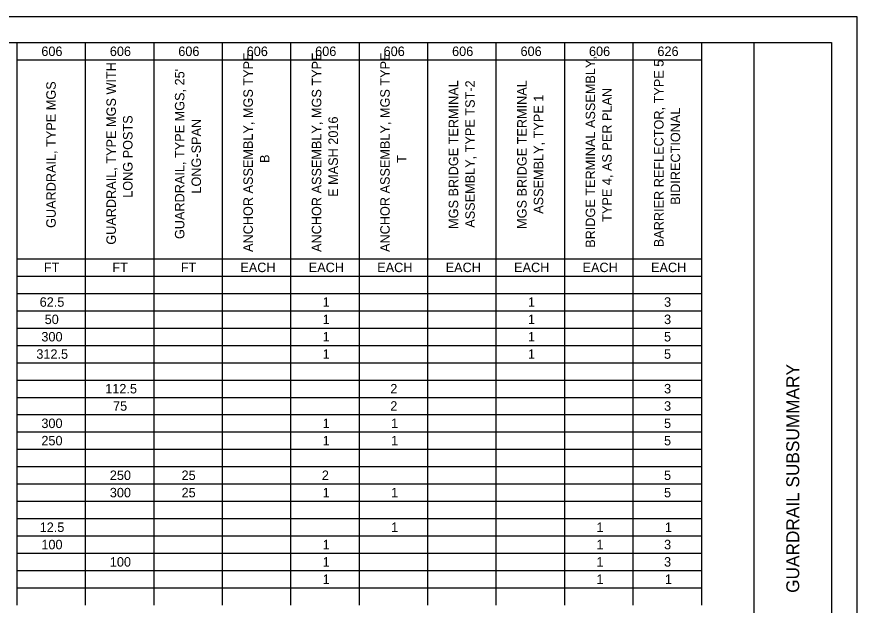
# Model space of a CAD drawing. Extents: x 0 to 34, y 0 to 22.
# Drawn here: x 17.69 to 34, y 10.59 to 22 of the extents above; entities that cross this region are included whole.
import ezdxf

# ---------------------------------------------------------------- set-up
doc = ezdxf.new("R2010")
doc.units = 0
for name, color, linetype in [('SH_Border', 7, 'Continuous'), ('SH_Cut_Line', 7, 'Continuous'), ('SH_Data', 7, 'Continuous'), ('SH_Text', 7, 'Continuous')]:
    doc.layers.add(name, color=color, linetype=linetype)

msp = doc.modelspace()

# ---------------------------------------------------------------- linework, layer by layer
at = {"layer": 'SH_Border'}
msp.add_line((32, 0.5), (32, 21.5), dxfattribs=at)
msp.add_lwpolyline([(1.5, 21.5), (33.5, 21.5), (33.5, 0.5), (1.5, 0.5)], close=True, dxfattribs=at)
at = {"layer": 'SH_Cut_Line'}
msp.add_lwpolyline([(0, 0), (34, 0), (34, 22), (0, 22)], close=True, dxfattribs=at)
at = {"layer": 'SH_Text'}
for p, q in [((17.694, 21.499), (19.022, 21.499)), ((17.694, 21.499), (17.694, 21.163)), ((19.022, 21.499), (28.32, 21.499)), ((19.022, 21.499), (19.022, 21.163)), ((20.35, 21.499), (20.35, 21.163)), ((21.679, 21.499), (21.679, 21.163)), ((23.007, 21.499), (23.007, 21.163)), ((24.335, 21.499), (24.335, 21.163)), ((25.663, 21.499), (25.663, 21.163)), ((26.991, 21.499), (26.991, 21.163)), ((28.32, 21.499), (29.648, 21.499)), ((28.32, 21.499), (28.32, 21.163)), ((29.648, 21.499), (30.976, 21.499)), ((29.648, 21.499), (29.648, 21.163)), ((30.976, 21.499), (30.976, 21.163)), ((17.694, 21.163), (19.022, 21.163)), ((17.694, 21.163), (17.694, 20.827)), ((19.022, 21.163), (28.32, 21.163)), ((19.022, 21.163), (19.022, 20.827)), ((20.35, 21.163), (20.35, 20.827)), ((21.679, 21.163), (21.679, 20.827)), ((23.007, 21.163), (23.007, 20.827)), ((24.335, 21.163), (24.335, 20.827)), ((25.663, 21.163), (25.663, 20.827)), ((26.991, 21.163), (26.991, 20.827)), ((28.32, 21.163), (29.648, 21.163)), ((28.32, 21.163), (28.32, 20.827)), ((29.648, 21.163), (30.976, 21.163)), ((29.648, 21.163), (29.648, 20.827)), ((30.976, 21.163), (30.976, 20.827)), ((17.694, 20.827), (17.694, 20.491)), ((19.022, 20.827), (19.022, 20.491)), ((20.35, 20.827), (20.35, 20.491)), ((21.679, 20.827), (21.679, 20.491)), ((23.007, 20.827), (23.007, 20.491)), ((24.335, 20.827), (24.335, 20.491)), ((25.663, 20.827), (25.663, 20.491)), ((26.991, 20.827), (26.991, 20.491)), ((28.32, 20.827), (28.32, 20.491)), ((29.648, 20.827), (29.648, 20.491)), ((30.976, 20.827), (30.976, 20.491)), ((17.694, 20.491), (17.694, 20.155)), ((19.022, 20.491), (19.022, 20.155)), ((20.35, 20.491), (20.35, 20.155)), ((21.679, 20.491), (21.679, 20.155)), ((23.007, 20.491), (23.007, 20.155)), ((24.335, 20.491), (24.335, 20.155)), ((25.663, 20.491), (25.663, 20.155)), ((26.991, 20.491), (26.991, 20.155)), ((28.32, 20.491), (28.32, 20.155)), ((29.648, 20.491), (29.648, 20.155)), ((30.976, 20.491), (30.976, 20.155)), ((17.694, 20.155), (17.694, 19.819)), ((19.022, 20.155), (19.022, 19.819)), ((20.35, 20.155), (20.35, 19.819)), ((21.679, 20.155), (21.679, 19.819)), ((23.007, 20.155), (23.007, 19.819)), ((24.335, 20.155), (24.335, 19.819)), ((25.663, 20.155), (25.663, 19.819)), ((26.991, 20.155), (26.991, 19.819)), ((28.32, 20.155), (28.32, 19.819)), ((29.648, 20.155), (29.648, 19.819)), ((30.976, 20.155), (30.976, 19.819)), ((17.694, 19.819), (17.694, 19.483)), ((19.022, 19.819), (19.022, 19.483)), ((20.35, 19.819), (20.35, 19.483)), ((21.679, 19.819), (21.679, 19.483)), ((23.007, 19.819), (23.007, 19.483)), ((24.335, 19.819), (24.335, 19.483)), ((25.663, 19.819), (25.663, 19.483)), ((26.991, 19.819), (26.991, 19.483)), ((28.32, 19.819), (28.32, 19.483)), ((29.648, 19.819), (29.648, 19.483)), ((30.976, 19.819), (30.976, 19.483)), ((17.694, 19.483), (17.694, 19.147)), ((19.022, 19.483), (19.022, 19.147)), ((20.35, 19.483), (20.35, 19.147)), ((21.679, 19.483), (21.679, 19.147)), ((23.007, 19.483), (23.007, 19.147)), ((24.335, 19.483), (24.335, 19.147)), ((25.663, 19.483), (25.663, 19.147)), ((26.991, 19.483), (26.991, 19.147)), ((28.32, 19.483), (28.32, 19.147)), ((29.648, 19.483), (29.648, 19.147)), ((30.976, 19.483), (30.976, 19.147)), ((17.694, 19.147), (17.694, 18.315)), ((19.022, 19.147), (19.022, 18.315)), ((20.35, 19.147), (20.35, 18.315)), ((21.679, 19.147), (21.679, 18.315)), ((23.007, 19.147), (23.007, 18.315)), ((24.335, 19.147), (24.335, 18.315)), ((25.663, 19.147), (25.663, 18.315)), ((26.991, 19.147), (26.991, 18.315)), ((28.32, 19.147), (28.32, 18.315)), ((29.648, 19.147), (29.648, 18.315)), ((30.976, 19.147), (30.976, 18.315)), ((17.694, 18.315), (17.694, 17.307)), ((19.022, 18.315), (19.022, 17.307)), ((20.35, 18.315), (20.35, 17.307)), ((21.679, 18.315), (21.679, 17.307)), ((23.007, 18.315), (23.007, 17.307)), ((24.335, 18.315), (24.335, 17.307)), ((25.663, 18.315), (25.663, 17.307)), ((26.991, 18.315), (26.991, 17.307)), ((28.32, 18.315), (28.32, 17.307)), ((29.648, 18.315), (29.648, 17.307)), ((30.976, 18.315), (30.976, 17.307)), ((17.694, 17.307), (19.022, 17.307)), ((17.694, 17.307), (17.694, 16.971)), ((19.022, 17.307), (28.32, 17.307)), ((19.022, 17.307), (19.022, 16.971)), ((20.35, 17.307), (20.35, 16.971)), ((21.679, 17.307), (21.679, 16.971)), ((23.007, 17.307), (23.007, 16.971)), ((24.335, 17.307), (24.335, 16.971)), ((25.663, 17.307), (25.663, 16.971)), ((26.991, 17.307), (26.991, 16.971)), ((28.32, 17.307), (29.648, 17.307)), ((28.32, 17.307), (28.32, 16.971)), ((29.648, 17.307), (30.976, 17.307)), ((29.648, 17.307), (29.648, 16.971)), ((30.976, 17.307), (30.976, 16.971)), ((17.694, 16.971), (19.022, 16.971)), ((17.694, 16.971), (17.694, 16.299)), ((19.022, 16.971), (28.32, 16.971)), ((19.022, 16.971), (19.022, 16.299)), ((20.35, 16.971), (20.35, 16.299)), ((21.679, 16.971), (21.679, 16.299)), ((23.007, 16.971), (23.007, 16.299)), ((24.335, 16.971), (24.335, 16.299)), ((25.663, 16.971), (25.663, 16.299)), ((26.991, 16.971), (26.991, 16.299)), ((28.32, 16.971), (29.648, 16.971)), ((28.32, 16.971), (28.32, 16.299)), ((29.648, 16.971), (30.976, 16.971)), ((29.648, 16.971), (29.648, 16.299)), ((30.976, 16.971), (30.976, 16.299)), ((17.694, 16.635), (19.022, 16.635)), ((19.022, 16.635), (28.32, 16.635)), ((28.32, 16.635), (29.648, 16.635)), ((29.648, 16.635), (30.976, 16.635)), ((17.694, 16.299), (19.022, 16.299)), ((17.694, 16.299), (17.694, 15.962)), ((19.022, 16.299), (28.32, 16.299)), ((19.022, 16.299), (19.022, 15.962)), ((20.35, 16.299), (20.35, 15.962)), ((21.679, 16.299), (21.679, 15.962)), ((23.007, 16.299), (23.007, 15.962)), ((24.335, 16.299), (24.335, 15.962)), ((25.663, 16.299), (25.663, 15.962)), ((26.991, 16.299), (26.991, 15.962)), ((28.32, 16.299), (29.648, 16.299)), ((28.32, 16.299), (28.32, 15.962)), ((29.648, 16.299), (30.976, 16.299)), ((29.648, 16.299), (29.648, 15.962)), ((30.976, 16.299), (30.976, 15.962)), ((17.694, 15.962), (19.022, 15.962)), ((17.694, 15.962), (17.694, 14.282)), ((19.022, 15.962), (28.32, 15.962)), ((19.022, 15.962), (19.022, 14.282)), ((20.35, 15.962), (20.35, 14.282)), ((21.679, 15.962), (21.679, 14.282)), ((23.007, 15.962), (23.007, 14.282)), ((24.335, 15.962), (24.335, 14.282)), ((25.663, 15.962), (25.663, 14.282)), ((26.991, 15.962), (26.991, 14.282)), ((28.32, 15.962), (29.648, 15.962)), ((28.32, 15.962), (28.32, 14.282)), ((29.648, 15.962), (30.976, 15.962)), ((29.648, 15.962), (29.648, 14.282)), ((30.976, 15.962), (30.976, 14.282)), ((17.694, 15.626), (19.022, 15.626)), ((19.022, 15.626), (28.32, 15.626)), ((28.32, 15.626), (29.648, 15.626)), ((29.648, 15.626), (30.976, 15.626)), ((17.694, 15.29), (19.022, 15.29)), ((19.022, 15.29), (28.32, 15.29)), ((28.32, 15.29), (29.648, 15.29)), ((29.648, 15.29), (30.976, 15.29)), ((17.694, 14.954), (19.022, 14.954)), ((19.022, 14.954), (28.32, 14.954)), ((28.32, 14.954), (29.648, 14.954)), ((29.648, 14.954), (30.976, 14.954)), ((17.694, 14.618), (19.022, 14.618)), ((19.022, 14.618), (28.32, 14.618)), ((28.32, 14.618), (29.648, 14.618)), ((29.648, 14.618), (30.976, 14.618)), ((17.694, 14.282), (19.022, 14.282)), ((17.694, 14.282), (17.694, 13.61)), ((19.022, 14.282), (28.32, 14.282)), ((19.022, 14.282), (19.022, 13.61)), ((20.35, 14.282), (20.35, 13.61)), ((21.679, 14.282), (21.679, 13.61)), ((23.007, 14.282), (23.007, 13.61)), ((24.335, 14.282), (24.335, 13.61)), ((25.663, 14.282), (25.663, 13.61)), ((26.991, 14.282), (26.991, 13.61)), ((28.32, 14.282), (29.648, 14.282)), ((28.32, 14.282), (28.32, 13.61)), ((29.648, 14.282), (30.976, 14.282)), ((29.648, 14.282), (29.648, 13.61)), ((30.976, 14.282), (30.976, 13.61)), ((17.694, 13.946), (19.022, 13.946)), ((19.022, 13.946), (28.32, 13.946)), ((28.32, 13.946), (29.648, 13.946)), ((29.648, 13.946), (30.976, 13.946)), ((17.694, 13.61), (19.022, 13.61)), ((17.694, 13.61), (17.694, 12.938)), ((19.022, 13.61), (28.32, 13.61)), ((19.022, 13.61), (19.022, 12.938)), ((20.35, 13.61), (20.35, 12.938)), ((21.679, 13.61), (21.679, 12.938)), ((23.007, 13.61), (23.007, 12.938)), ((24.335, 13.61), (24.335, 12.938)), ((25.663, 13.61), (25.663, 12.938)), ((26.991, 13.61), (26.991, 12.938)), ((28.32, 13.61), (29.648, 13.61)), ((28.32, 13.61), (28.32, 12.938)), ((29.648, 13.61), (30.976, 13.61)), ((29.648, 13.61), (29.648, 12.938)), ((30.976, 13.61), (30.976, 12.938)), ((17.694, 13.274), (19.022, 13.274)), ((19.022, 13.274), (28.32, 13.274)), ((28.32, 13.274), (29.648, 13.274)), ((29.648, 13.274), (30.976, 13.274)), ((17.694, 12.938), (19.022, 12.938)), ((17.694, 12.938), (17.694, 12.602)), ((19.022, 12.938), (28.32, 12.938)), ((19.022, 12.938), (19.022, 12.602)), ((20.35, 12.938), (20.35, 12.602)), ((21.679, 12.938), (21.679, 12.602)), ((23.007, 12.938), (23.007, 12.602)), ((24.335, 12.938), (24.335, 12.602)), ((25.663, 12.938), (25.663, 12.602)), ((26.991, 12.938), (26.991, 12.602)), ((28.32, 12.938), (29.648, 12.938)), ((28.32, 12.938), (28.32, 12.602)), ((29.648, 12.938), (30.976, 12.938)), ((29.648, 12.938), (29.648, 12.602)), ((30.976, 12.938), (30.976, 12.602)), ((17.694, 12.602), (19.022, 12.602)), ((17.694, 12.602), (17.694, 11.93)), ((19.022, 12.602), (28.32, 12.602)), ((19.022, 12.602), (19.022, 11.93)), ((20.35, 12.602), (20.35, 11.93)), ((21.679, 12.602), (21.679, 11.93)), ((23.007, 12.602), (23.007, 11.93)), ((24.335, 12.602), (24.335, 11.93)), ((25.663, 12.602), (25.663, 11.93)), ((26.991, 12.602), (26.991, 11.93)), ((28.32, 12.602), (29.648, 12.602)), ((28.32, 12.602), (28.32, 11.93)), ((29.648, 12.602), (30.976, 12.602)), ((29.648, 12.602), (29.648, 11.93)), ((30.976, 12.602), (30.976, 11.93)), ((17.694, 12.266), (19.022, 12.266)), ((19.022, 12.266), (28.32, 12.266)), ((28.32, 12.266), (29.648, 12.266)), ((29.648, 12.266), (30.976, 12.266)), ((17.694, 11.93), (19.022, 11.93)), ((17.694, 11.93), (17.694, 11.594)), ((19.022, 11.93), (28.32, 11.93)), ((19.022, 11.93), (19.022, 11.594)), ((20.35, 11.93), (20.35, 11.594)), ((21.679, 11.93), (21.679, 11.594)), ((23.007, 11.93), (23.007, 11.594)), ((24.335, 11.93), (24.335, 11.594)), ((25.663, 11.93), (25.663, 11.594)), ((26.991, 11.93), (26.991, 11.594)), ((28.32, 11.93), (29.648, 11.93)), ((28.32, 11.93), (28.32, 11.594)), ((29.648, 11.93), (30.976, 11.93)), ((29.648, 11.93), (29.648, 11.594)), ((30.976, 11.93), (30.976, 11.594)), ((17.694, 11.594), (19.022, 11.594)), ((17.694, 11.594), (17.694, 10.586)), ((19.022, 11.594), (28.32, 11.594)), ((19.022, 11.594), (19.022, 10.586)), ((20.35, 11.594), (20.35, 10.586)), ((21.679, 11.594), (21.679, 10.586)), ((23.007, 11.594), (23.007, 10.586)), ((24.335, 11.594), (24.335, 10.586)), ((25.663, 11.594), (25.663, 10.586)), ((26.991, 11.594), (26.991, 10.586)), ((28.32, 11.594), (29.648, 11.594)), ((28.32, 11.594), (28.32, 10.586)), ((29.648, 11.594), (30.976, 11.594)), ((29.648, 11.594), (29.648, 10.586)), ((30.976, 11.594), (30.976, 10.586)), ((17.694, 11.258), (19.022, 11.258)), ((19.022, 11.258), (28.32, 11.258)), ((28.32, 11.258), (29.648, 11.258)), ((29.648, 11.258), (30.976, 11.258)), ((17.694, 10.922), (19.022, 10.922)), ((19.022, 10.922), (28.32, 10.922)), ((28.32, 10.922), (29.648, 10.922)), ((29.648, 10.922), (30.976, 10.922))]:
    msp.add_line(p, q, dxfattribs=at)

# ---------------------------------------------------------------- texts
at = {"layer": 'SH_Data'}
msp.add_text('GUARDRAIL SUBSUMMARY', height=0.25, rotation=90, dxfattribs=at).set_placement((32.875, 10.825))
at = {"layer": 'SH_Text'}
for s, p in [('606', (18.17, 21.239)), ('606', (19.499, 21.239)), ('606', (20.827, 21.239)), ('606', (22.155, 21.239)), ('606', (23.483, 21.239)), ('606', (24.811, 21.239)), ('606', (26.14, 21.239)), ('606', (27.468, 21.239)), ('606', (28.796, 21.239)), ('626', (30.124, 21.239)), ('FT', (18.219, 17.047)), ('FT', (19.547, 17.047)), ('FT', (20.876, 17.047)), ('EACH', (22.031, 17.047)), ('EACH', (23.359, 17.047)), ('EACH', (24.687, 17.047)), ('EACH', (26.015, 17.047)), ('EACH', (27.343, 17.047)), ('EACH', (28.671, 17.047)), ('EACH', (30, 17.047)), ('62.5', (18.138, 16.375)), ('1', (23.628, 16.375)), ('1', (27.612, 16.375)), ('3', (30.253, 16.375)), ('50', (18.235, 16.039)), ('1', (23.628, 16.039)), ('1', (27.612, 16.039)), ('3', (30.253, 16.039)), ('300', (18.171, 15.702)), ('1', (23.628, 15.702)), ('1', (27.612, 15.702)), ('5', (30.252, 15.702)), ('312.5', (18.073, 15.366)), ('1', (23.628, 15.366)), ('1', (27.612, 15.366)), ('5', (30.252, 15.366)), ('112.5', (19.41, 14.694)), ('2', (24.941, 14.694)), ('3', (30.253, 14.694)), ('75', (19.562, 14.358)), ('2', (24.941, 14.358)), ('3', (30.253, 14.358)), ('300', (18.171, 14.022)), ('1', (23.628, 14.022)), ('1', (24.956, 14.022)), ('5', (30.252, 14.022)), ('250', (18.171, 13.686)), ('1', (23.628, 13.686)), ('1', (24.956, 13.686)), ('5', (30.252, 13.686)), ('250', (19.499, 13.014)), ('25', (20.891, 13.014)), ('2', (23.613, 13.014)), ('5', (30.252, 13.014)), ('300', (19.499, 12.678)), ('25', (20.891, 12.678)), ('1', (23.628, 12.678)), ('1', (24.956, 12.678)), ('5', (30.252, 12.678)), ('12.5', (18.138, 12.006)), ('1', (24.956, 12.006)), ('1', (28.941, 12.006)), ('1', (30.269, 12.006)), ('100', (18.171, 11.67)), ('1', (23.628, 11.67)), ('1', (28.941, 11.67)), ('3', (30.253, 11.67)), ('100', (19.499, 11.334)), ('1', (23.628, 11.334)), ('1', (28.941, 11.334)), ('3', (30.253, 11.334)), ('1', (23.628, 10.998)), ('1', (28.941, 10.998)), ('1', (30.269, 10.998))]:
    msp.add_text(s, height=0.184, dxfattribs=at).set_placement(p)
for s, height, p in [('ANCHOR ASSEMBLY, MGS TYPE ', 0.18402, (22.274, 17.438)), ('ANCHOR ASSEMBLY, MGS TYPE ', 0.18402, (23.602, 17.438)), ('ANCHOR ASSEMBLY, MGS TYPE ', 0.18402, (24.93, 17.438)), ('BRIDGE TERMINAL ASSEMBLY, ', 0.18402, (28.915, 17.518)), ('GUARDRAIL, TYPE MGS WITH ', 0.18402, (19.617, 17.579)), ('BARRIER REFLECTOR, TYPE 5 ', 0.18402, (30.243, 17.531)), ("GUARDRAIL, TYPE MGS, 25' ", 0.18402, (20.946, 17.688)), ('GUARDRAIL, TYPE MGS', 0.18402, (18.45, 17.904)), ('MGS BRIDGE TERMINAL ', 0.18402, (26.258, 17.885)), ('ASSEMBLY, TYPE TST-2', 0.18402, (26.58, 17.908)), ('MGS BRIDGE TERMINAL ', 0.18402, (27.586, 17.885)), ('TYPE 4, AS PER PLAN', 0.18402, (29.237, 18.023)), ('ASSEMBLY, TYPE 1', 0.18402, (27.908, 18.178)), ('BIDIRECTIONAL', 0.18402, (30.565, 18.352)), ('LONG POSTS', 0.184, (19.939, 18.489)), ('LONG-SPAN', 0.184, (21.268, 18.571)), ('E MASH 2016', 0.18402, (23.924, 18.507)), ('B', 0.184, (22.596, 19.164)), ('T', 0.184, (25.252, 19.167))]:
    msp.add_text(s, height=height, rotation=90, dxfattribs=at).set_placement(p)

doc.saveas('drawing.dxf')
